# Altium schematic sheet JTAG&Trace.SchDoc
size A4; Revision: B.2
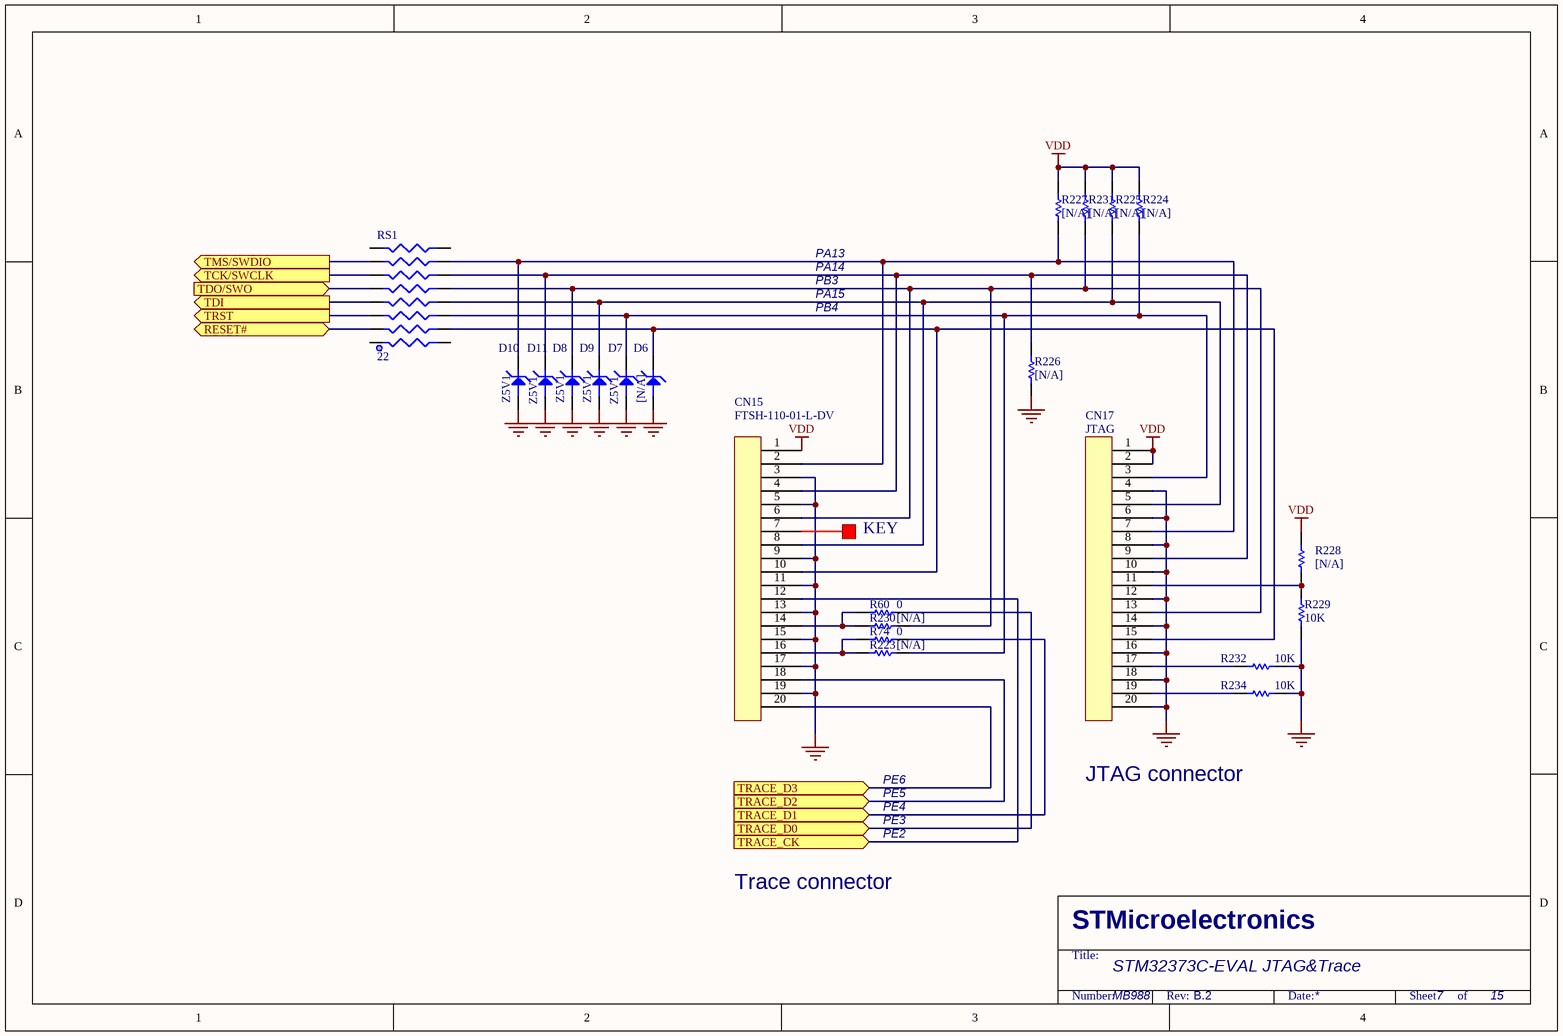
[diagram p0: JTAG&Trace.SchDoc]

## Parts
CN15  FTSH-110-01-L-DV  [FTSH-110-01-L-DV]
CN17  JTAG  [IDC20S]
D6  [N/A]  [SOT-23]
D7  Z5V1  [SOT-23]
D8  Z5V1  [SOT-23]
D9  Z5V1  [SOT-23]
D10  Z5V1  [SOT-23]
D11  Z5V1  [SOT-23]
R60  0  [0603R]
R74  0  [0603R]
R223  [N/A]  [0603R]
R224  [N/A]  [0603R]
R225  [N/A]  [0603R]
R226  [N/A]  [0603R]
R227  [N/A]  [0603R]
R228  [N/A]  [0603R]
R229  10K  [0603R]
R230  [N/A]  [0603R]
R231  [N/A]  [0603R]
R232  10K  [0603R]
R234  10K  [0603R]
RS1  22  [RES8B_0402]

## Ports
RESET# (bidir), TCK/SWCLK (out), TDI (out), TDO/SWO (in), TMS/SWDIO (out), TRACE_CK (in), TRACE_D0 (in), TRACE_D1 (in), TRACE_D2 (in), TRACE_D3 (in), TRST (out)

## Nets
GND: CN15.3 CN15.5 CN15.9 CN15.11 CN15.13 CN15.15 CN15.17 CN15.19 CN17.4 CN17.6 CN17.8 CN17.10 CN17.12 CN17.14 CN17.16 CN17.18 CN17.20 D6.2 D7.2 D8.2 D9.2 D10.2 D11.2 R226.1 R229.1 R232.1 R234.1
VDD: CN15.1 CN17.1 CN17.2 R224.2 R225.2 R227.2 R228.2 R231.2
RESET#: RS1.3 ; port RESET#
TCK/SWCLK: RS1.11 ; port TCK/SWCLK
TDI: RS1.7 ; port TDI
TDO/SWO: RS1.9 ; port TDO/SWO
TMS/SWDIO: RS1.13 ; port TMS/SWDIO
TRACE_CK: CN15.12 ; port TRACE_CK
TRACE_D0: R60.2 ; port TRACE_D0
TRACE_D1: R74.2 ; port TRACE_D1
TRACE_D2: CN15.18 ; port TRACE_D2
TRACE_D3: CN15.20 ; port TRACE_D3
TRST: RS1.5 ; port TRST
NetCN15_2: CN15.2 CN17.7 D10.3 R227.1 RS1.14
NetCN15_4: CN15.4 CN17.9 D11.3 R226.2 RS1.12
NetCN15_6: CN15.6 CN17.13 D8.3 R230.2 R231.1 RS1.10
NetCN15_8: CN15.8 CN17.5 D9.3 R225.1 RS1.8
NetCN15_10: CN15.10 CN17.15 D6.3 RS1.4
NetCN15_14: CN15.14 R60.1 R230.1
NetCN15_16: CN15.16 R74.1 R223.1
NetCN17_3: CN17.3 D7.3 R223.2 R224.1 RS1.6
NetCN17_11: CN17.11 R228.1 R229.2
NetCN17_17: CN17.17 R232.2
NetCN17_19: CN17.19 R234.2

Not connected (* = marked no-connect by the designer): CN15 7; RS1 1 2 15 16

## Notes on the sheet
- PA13
- PA14
- PB3
- PA15
- PB4
- KEY
- PE6
- JTAG connector
- PE5
- PE4
- PE3
- PE2
- Trace connector
- STM32373C-EVAL JTAG&Trace
- MB988
- 7
- 15

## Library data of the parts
CN15 CN17 = 20PIN1
D6-D11 = BATS5V6
R60 R74 R223-R232 R234 = Res1: Resistor; Value: 1K
RS1 = RES8B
